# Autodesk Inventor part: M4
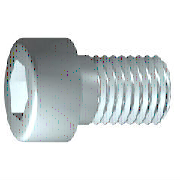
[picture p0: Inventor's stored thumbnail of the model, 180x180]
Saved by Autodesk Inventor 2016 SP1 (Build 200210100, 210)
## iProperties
IsCustomPart: 0
Created: 2016-04
Part Number: M4
Material: 강철, 연강
Description: 6각머리 태핑 나사
Document SubType Name: Modeling
Standard: KS B 1003
Designer: mdu
Standards Organization: KS
Language: ko-KR
Size Designation: M 4 x 10
Categories: <MemberInstance><Categories><Category DisplayName="조임쇠" InternalName="e4da775c-781d-43d5-af7c-5136215cf5a6" Mnemonic="FSTN"><Category DisplayName="볼트" InternalN
Density: 7.86 g/cm^3
Mass: 2.0371 g
Surface Area: 3.0572 cm^2
Volume: 0.259174 cm^3
Appearance: 금속 1800F 열
Author: mdu
Revision Number: 1
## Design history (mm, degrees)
sketch "스케치1"
  geometry: L1 (-1, 0)-(10, 0); L2 (10, 0)-(10, 2); L3 (10, 2)-(1.75, 2); L4 (1.75, 2)-(1.32, 2); L5 (1.32, 2)-(0, 2); L6 (0, 2)-(0, 3.5); L7 (0, 3.5)-(-4, 3.5); L8 (-4, 3.5)-(-4, 1.732); L9 (-4, 1.732)-(-2, 1.732); L10 (-2, 1.732)-(-1, 0); L11 (-6.8, 0)-(12.8, 0) reference; L12 (0, -0.7)-(0, 4.2) reference; L13 (1.75, 2)-(0, 2)
  constraints: 22 end point, 6 parallel, 2 collinear, 2 perpendicular, 1 horizontal, 1 point on line
  dimensions: "d1" = 8.25 distance from line of L3.end L2 (= GEL); "d2" = 0.42952 distance of L4.end L3.end (computed from GAL); "d3" = 4 distance between parallel lines of L8 L6 (= KOH); "d4" = 2 distance of L8.end L9.end (= INTI); "d5" = 60 deg angle of L10 L1; "d6" = 4 diameter of L3 L1 (= GD); "d7" = 4 diameter of L5 L1 (= BDM); "d8" = 3.4641 diameter of L9 L1 (= 1.1547 x SW); "d9" = 7 diameter of L7 L1 (= KOD); "d26" = 10 distance between parallel lines of L12 L2 (= NLG)
revolve "본체" sketch "스케치1" stored, may be unused: angle "d10" = 90 deg
sketch "스케치2"
  geometry: L1 (0, -4.9)-(0, 4.9) reference; L2 (-4.9, 0)-(4.9, 0) reference; L3 (1.732, 0)-(0.866, -1.5); L4 (0.866, -1.5)-(-0.866, -1.5); L5 (-0.866, -1.5)-(-1.732, 0); L6 (-1.732, 0)-(-0.866, 1.5); L7 (-0.866, 1.5)-(0.866, 1.5); L8 (0.866, 1.5)-(1.732, 0); 2 further points
  constraints: 12 end point, 1 coincident, 1 horizontal alignment, 1 point on line, 12 other
extrude "슬롯" join sketch "스케치2" stored distance "d11" = 10; taper "d12" = 0 deg
workplane "Work Plane1"
fillet "Fillet2" dims "d30" = 0.1 (= R)
body "Solid1"
fillet "모깎기1" dims "d17" = 0.4 (= RR)
feature "스레드" dims "d13" = 8.25 (= GEL), "d14" = 0
chamfer "모따기1" distance "d15" = 0.42941 (= -0.5 x SPD + 0.5 x GD); stored, may be unused: second distance "d16" = 0.42941 (= GUL), angle "d27" = 45 deg
other parameters: "GD" = 4 (= NND) [user parameter; used in 2 equation terms], "NLG" = 10 [user parameter; used in 1 equation term], "GEL" = 8.25 [user parameter; used in 2 equation terms], "KOD" = 7 [user parameter; used in 1 equation term], "KOH" = 4 [user parameter; used in 1 equation term], "INTI" = 2 [user parameter; used in 1 equation term], "GAL" = 0.42941 (= 0.61345 x PTC) [user parameter; used in 1 equation term], "GUL" = 0.42941 (= 0.61345 x PTC) [user parameter; used in 1 equation term], "BDM" = 4 (= NND) [user parameter; used in 1 equation term], "SW" = 3 [user parameter; used in 2 equation terms], "RR" = 0.4 [user parameter; used in 1 equation term], "SPD" = 3.14117 (= NND - 1.2269 x PTC) [user parameter; used in 1 equation term], "d19" = 0, "d28" = 0, "d29" = 0, "R" = 0.1 [user parameter; used in 1 equation term], "PHH" = 0.2 [user parameter], "GD1" = 3.14117 (= THREADDIA - 1.2269 x PTC) [user parameter], "THREADDIA" = 4 [user parameter; used in 1 equation term], "FAWI" = 45 deg [user parameter], "TPU" = 14.28571 (computed from PTC) [user parameter], "PTC" = 0.7 [user parameter; used in 5 equation terms], "NND" = 4 [user parameter; used in 3 equation terms], "TOA" = 30 deg [user parameter], "E0" = 3.465 (= 1.155 x SW) [user parameter]
